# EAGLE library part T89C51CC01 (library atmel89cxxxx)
80c51 256B+1k RAM; 32k ProgrammFlash 2k EEPROM 8x10bit AD-converter Full CAN 40MHz (z.B. bei Spoerle)
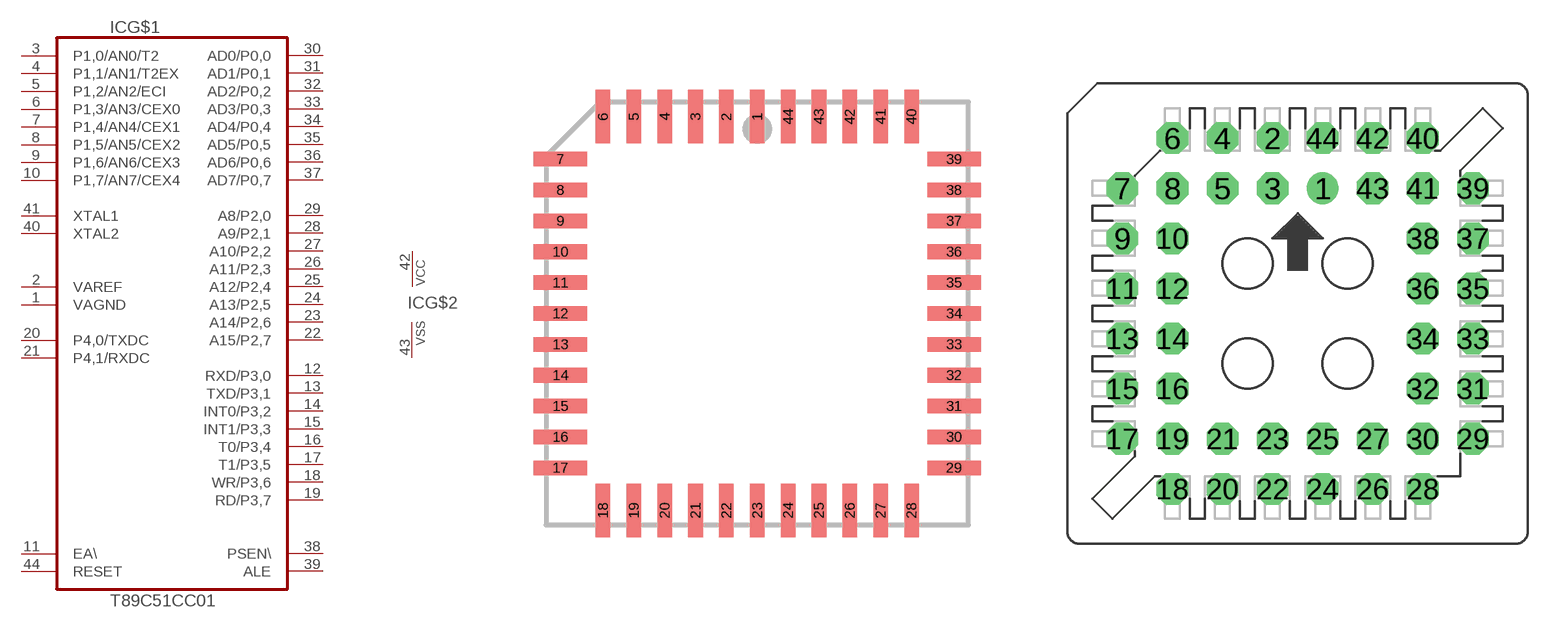
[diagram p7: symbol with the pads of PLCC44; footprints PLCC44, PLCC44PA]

Designator prefix IC; gates G$1=C51CC01 G$2=VCCVSS

## T89C51CC01SMD-SOCKET  [PLCC44]
1  G$1:VAGND  pas
2  G$1:VAREF  pas
3  G$1:P1,0/AN0/T2
4  G$1:P1,1/AN1/T2EX
5  G$1:P1,2/AN2/ECI
6  G$1:P1,3/AN3/CEX0
7  G$1:P1,4/AN4/CEX1
8  G$1:P1,5/AN5/CEX2
9  G$1:P1,6/AN6/CEX3
10  G$1:P1,7/AN7/CEX4
11  G$1:EA\  in
12  G$1:RXD/P3,0
13  G$1:TXD/P3,1
14  G$1:INT0/P3,2
15  G$1:INT1/P3,3
16  G$1:T0/P3,4
17  G$1:T1/P3,5
18  G$1:WR/P3,6
19  G$1:RD/P3,7
20  G$1:P4,0/TXDC
21  G$1:P4,1/RXDC
22  G$1:A15/P2,7
23  G$1:A14/P2,6
24  G$1:A13/P2,5
25  G$1:A12/P2,4
26  G$1:A11/P2,3
27  G$1:A10/P2,2
28  G$1:A9/P2,1
29  G$1:A8/P2,0
30  G$1:AD0/P0,0
31  G$1:AD1/P0,1
32  G$1:AD2/P0,2
33  G$1:AD3/P0,3
34  G$1:AD4/P0,4
35  G$1:AD5/P0,5
36  G$1:AD6/P0,6
37  G$1:AD7/P0,7
38  G$1:PSEN\  out
39  G$1:ALE  out
40  G$1:XTAL2  pas
41  G$1:XTAL1  pas
42  G$2:VCC  pwr
43  G$2:VSS  pwr
44  G$1:RESET  in

## T89C51CC01PLCC-SOCKET  [PLCC44PA]
Pads as for PLCC44

## Footprint PLCC44 (pad centres in mm)
smd 0.6 x 2.2: 1 0,8.1; 2 -1.27,8.1; 3 -2.54,8.1; 4 -3.81,8.1; 5 -5.08,8.1; 6 -6.35,8.1; 18 -6.35,-8.1; 19 -5.08,-8.1; 20 -3.81,-8.1; 21 -2.54,-8.1; 22 -1.27,-8.1; 23 0,-8.1; 24 1.27,-8.1; 25 2.54,-8.1; 26 3.81,-8.1; 27 5.08,-8.1; 28 6.35,-8.1; 40 6.35,8.1; 41 5.08,8.1; 42 3.81,8.1; 43 2.54,8.1; 44 1.27,8.1
smd 2.2 x 0.6: 7 -8.1,6.35; 8 -8.1,5.08; 9 -8.1,3.81; 10 -8.1,2.54; 11 -8.1,1.27; 12 -8.1,0; 13 -8.1,-1.27; 14 -8.1,-2.54; 15 -8.1,-3.81; 16 -8.1,-5.08; 17 -8.1,-6.35; 29 8.1,-6.35; 30 8.1,-5.08; 31 8.1,-3.81; 32 8.1,-2.54; 33 8.1,-1.27; 34 8.1,0; 35 8.1,1.27; 36 8.1,2.54; 37 8.1,3.81; 38 8.1,5.08; 39 8.1,6.35

## Footprint PLCC44PA (pad centres in mm)
drill 0.813 pad 1.6 round: 1 1.27,6.35
drill 0.813 pad 1.6 octagon: 2 -1.27,8.89; 3 -1.27,6.35; 4 -3.81,8.89; 5 -3.81,6.35; 6 -6.35,8.89; 7 -8.89,6.35; 8 -6.35,6.35; 9 -8.89,3.81; 10 -6.35,3.81; 11 -8.89,1.27; 12 -6.35,1.27; 13 -8.89,-1.27; 14 -6.35,-1.27; 15 -8.89,-3.81; 16 -6.35,-3.81; 17 -8.89,-6.35; 18 -6.35,-8.89; 19 -6.35,-6.35; 20 -3.81,-8.89; 21 -3.81,-6.35; 22 -1.27,-8.89; 23 -1.27,-6.35; 24 1.27,-8.89; 25 1.27,-6.35; 26 3.81,-8.89; 27 3.81,-6.35; 28 6.35,-8.89; 29 8.89,-6.35; 30 6.35,-6.35; 31 8.89,-3.81; 32 6.35,-3.81; 33 8.89,-1.27; 34 6.35,-1.27; 35 8.89,1.27; 36 6.35,1.27; 37 8.89,3.81; 38 6.35,3.81; 39 8.89,6.35; 40 6.35,8.89; 41 6.35,6.35; 42 3.81,8.89; 43 3.81,6.35; 44 1.27,8.89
